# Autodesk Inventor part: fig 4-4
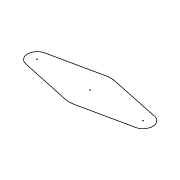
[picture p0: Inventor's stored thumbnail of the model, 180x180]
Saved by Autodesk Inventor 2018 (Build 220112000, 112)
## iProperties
Created: 2005-02
Part Number: fig 4-4
Document SubType Name: Modeling
Designer: CADCIM
Manufacturer: Standard
Standards Organization: Custom
Density: 1 g/cm^3
Material: Generic
Appearance: Default
Author: CADCIM
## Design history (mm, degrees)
sketch "Sketch1"
  geometry: L1 (-33.874, 5.844)-(-2.722, 12.469); L2 (2.595, 12.472)-(33.871, 5.852); L3 (-33.884, -5.902)-(-2.745, -12.585); L4 (2.595, -12.592)-(33.871, -5.972); A1 r 6.006 centre (-32.624, -0.03) between (-33.874, 5.844) and (-33.884, -5.902); A2 r 6.043 centre (32.619, -0.06) between (33.871, -5.972) and (33.871, 5.852); A3 r 12.81 centre (-0.057, -0.06) between (-2.745, -12.585) and (2.595, -12.592); A4 r 12.81 centre (-0.057, -0.06) between (2.595, 12.472) and (-2.722, 12.469)
  constraints: 8 end point, 8 point on circle, 8 tangent, 4 centre point, 1 other
